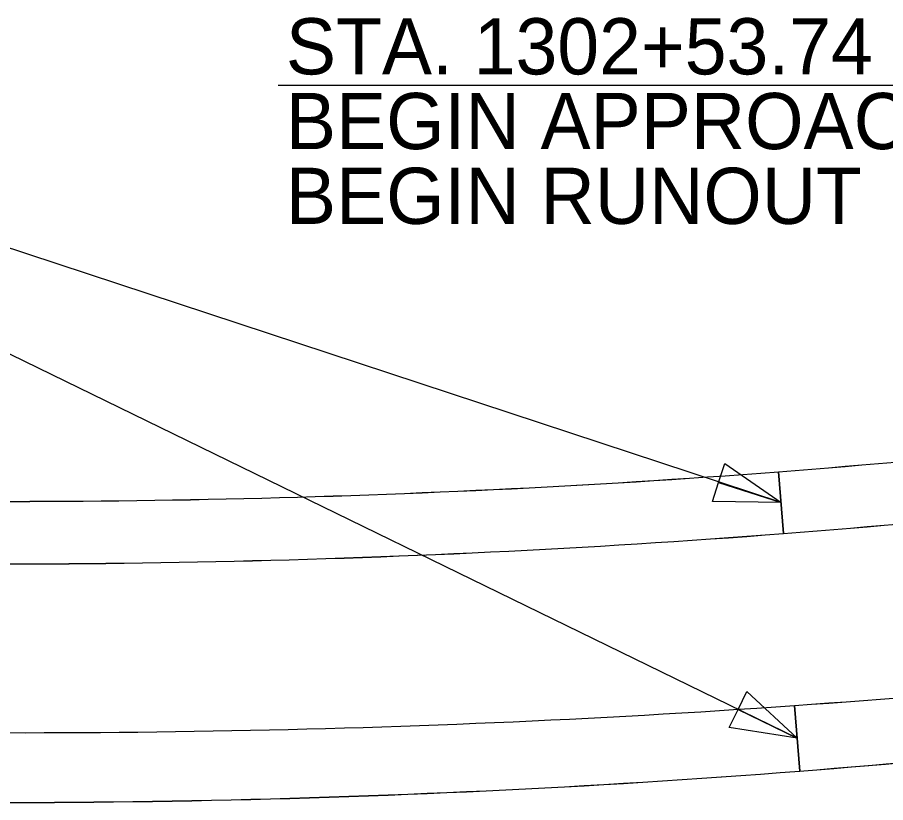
# Model space of a CAD drawing. Extents: x 10133 to 81668, y 7924 to 12255.
# Drawn here: x 18719.4 to 18979, y 9219.8 to 9454.5 of the extents above; entities that cross this region are included whole.
import ezdxf

# ---------------------------------------------------------------- set-up
doc = ezdxf.new("R2010")
doc.units = 0
doc.layers.add('RasterAttachment', color=7, linetype='Continuous')
doc.layers.add('Text', color=7, linetype='Continuous')

msp = doc.modelspace()

# ---------------------------------------------------------------- linework, layer by layer
at = {"layer": 'RasterAttachment'}
for p, q in [((18946.99, 9318.72), (18948.47, 9300.24)), ((18948.47, 9300.24), (18946.99, 9318.71)), ((18946.99, 9318.71), (18948.47, 9300.24)), ((18951.72, 9248.84), (18953.3, 9229.25)), ((18951.72, 9248.84), (18953.3, 9229.24)), ((18953.3, 9229.25), (18951.72, 9248.84))]:
    msp.add_line(p, q, dxfattribs=at)
for centre, radius, start, end in [((18587.46, 13823.14), 4518.75, 274.56356, 276.59163), ((18616.76, 13525.38), 4219.6, 274.48869, 276.66056), ((18714.23, 12374.25), 3064.38, 267.96964, 274.35626), ((18714.43, 12367.21), 3057.36, 267.96115, 274.36247), ((18595.05, 13711.56), 4425.45, 274.5806, 276.66383), ((18610.23, 13570.94), 4284.08, 274.52843, 276.68043), ((18711.83, 12374.21), 3083.07, 267.87838, 274.40211), ((18711.63, 12384.13), 3092.97, 267.88884, 274.39165), ((18740.03, 12315.06), 3073.51, 273.94942, 277.03255), ((18739.22, 12334.54), 3092.96, 273.93954, 277.00325), ((18720.34, 12543.8), 3303.07, 267.78434, 274.01696), ((18720.34, 12543.8), 3303.07, 267.78434, 274.01696), ((18691.46, 12568.29), 3349.29, 274.48373, 277.32972), ((18683.71, 12644.69), 3426.09, 274.51305, 277.26869), ((18711.77, 12318.88), 3099.06, 267.52295, 274.46996), ((18711.29, 12346.38), 3126.51, 267.55349, 274.43941)]:
    msp.add_arc(centre, radius, start, end, dxfattribs=at)
at = {"layer": 'Text'}
for p, q in [((18947.73, 9309.48), (18516.18, 9451.79)), ((18952.51, 9239.04), (18516.18, 9451.79)), ((19009.66, 9434.15), (18797.36, 9434.15))]:
    msp.add_line(p, q, dxfattribs=at)
for points in [[(18930.9, 9321.22), (18947.73, 9309.48), (18929.06, 9315.52)], [(18947.73, 9309.48), (18927.21, 9309.82), (18929.06, 9315.52)], [(18937.49, 9253.03), (18952.51, 9239.04), (18934.87, 9247.65)], [(18952.51, 9239.04), (18932.24, 9242.26), (18934.87, 9247.65)]]:
    msp.add_lwpolyline(points, close=True, dxfattribs=at)

# ---------------------------------------------------------------- texts
for s, p in [('STA. 1302+53.74', (18799.66, 9437.49)), ('BEGIN APPROACH', (18799.66, 9415.15)), ('BEGIN RUNOUT', (18799.66, 9392.8))]:
    msp.add_text(s, height=16.8, dxfattribs=at).set_placement(p)

doc.saveas('drawing.dxf')
